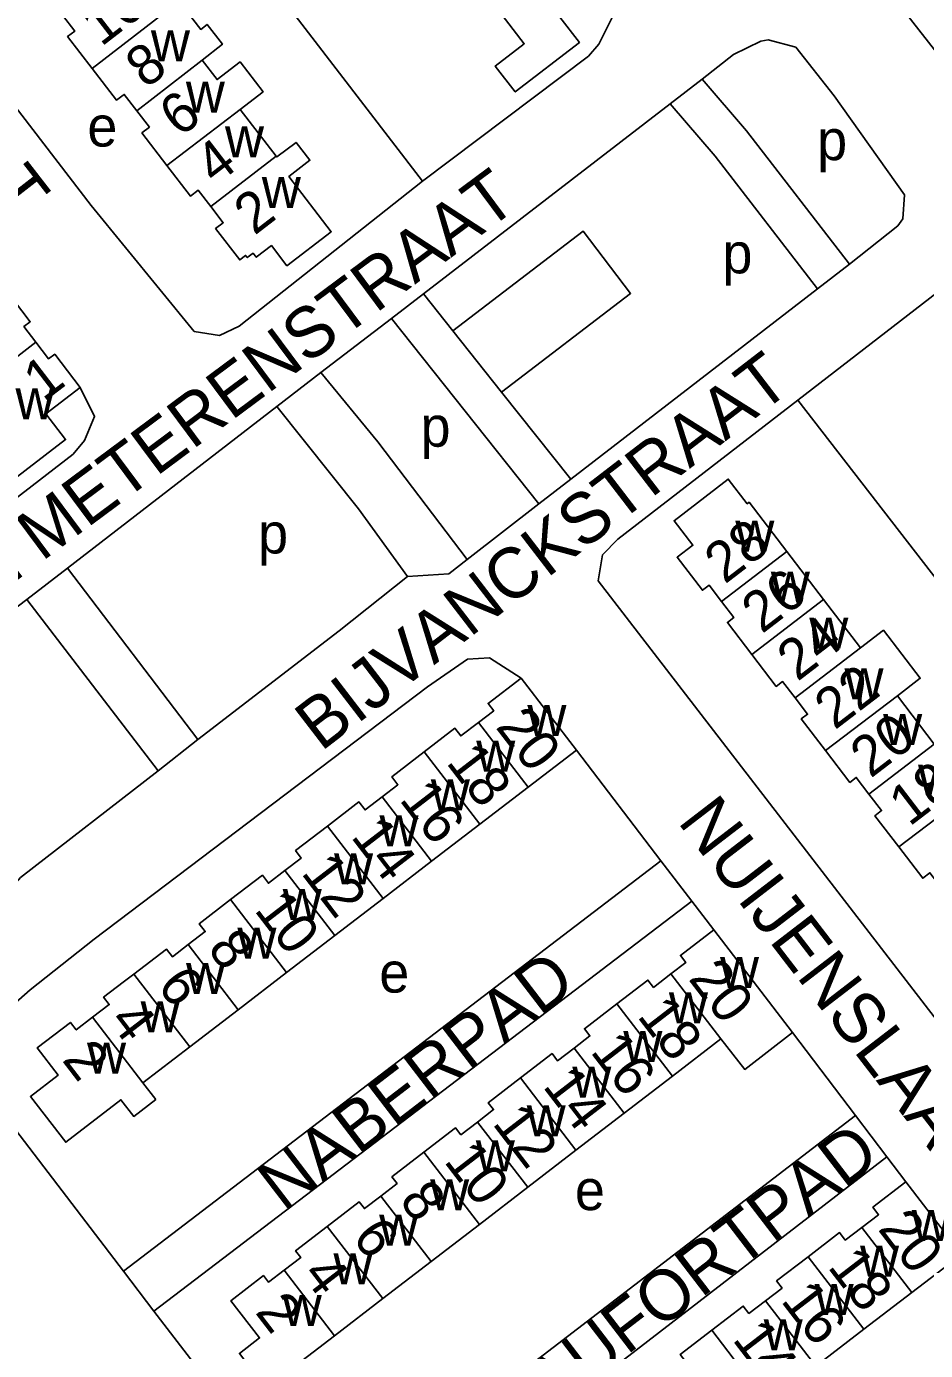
# Model space of a CAD drawing. Extents: x 158848 to 160613, y 385889 to 387762.
# Drawn here: x 159990.4 to 160079.5, y 386833.8 to 386965 of the extents above; entities that cross this region are included whole.
import ezdxf

# ---------------------------------------------------------------- set-up
doc = ezdxf.new("R2010")
doc.units = 0
for name, color, linetype in [('BLT_Basislijn', 7, 'Continuous'), ('BLT_Bebouwing', 7, 'Continuous'), ('BLT_Centroide', 7, 'Continuous'), ('BLT_Huisnummer', 7, 'Continuous'), ('BLT_Huisnummer_ tussenligend', 7, 'Continuous'), ('BLT_Onderverdeling_panden', 7, 'Continuous'), ('BLT_Straatnaam', 7, 'Continuous')]:
    doc.layers.add(name, color=color, linetype=linetype)

msp = doc.modelspace()

# ---------------------------------------------------------------- linework, layer by layer
at = {"layer": 'BLT_Basislijn'}
for p, q in [((160029.66, 386949.66), (160004.69, 386982.16)), ((160057.37, 386959.77), (160054.19, 386957.33)), ((160054.19, 386957.33), (160029.74, 386938.51)), ((160071.97, 386941.45), (160068.81, 386939.01)), ((160029.74, 386938.51), (160026.58, 386936.07)), ((160029.74, 386938.51), (160032.67, 386934.83)), ((160068.81, 386939.01), (160044.35, 386920.13)), ((160019.58, 386930.7), (160026.58, 386936.07)), ((160026.58, 386936.07), (160041.18, 386917.68)), ((160032.67, 386934.83), (160037.48, 386928.77)), ((160019.58, 386930.7), (160015.22, 386927.33)), ((160037.48, 386928.77), (160044.35, 386920.13)), ((160015.22, 386927.33), (159994.46, 386911.31)), ((160066.87, 386927.96), (160124.94, 386852.8)), ((160044.35, 386920.13), (160041.18, 386917.68)), ((160034.09, 386912.18), (160041.18, 386917.68)), ((159990.43, 386908.21), (159994.46, 386911.31)), ((159994.46, 386911.31), (160007.38, 386894.32)), ((160003.44, 386891.23), (159990.43, 386908.21)), ((160007.38, 386894.32), (160003.44, 386891.23)), ((160053.29, 386882.32), (160044.91, 386893.29)), ((160000.02, 386841.63), (160053.29, 386882.32)), ((160056.34, 386878.32), (160053.29, 386882.32)), ((160003.02, 386837.69), (160056.34, 386878.32)), ((160058.52, 386875.47), (160056.34, 386878.32)), ((160072.57, 386857.06), (160066.34, 386865.3)), ((160019.47, 386816.36), (160072.57, 386857.06)), ((160075.68, 386852.96), (160072.57, 386857.06)), ((160075.68, 386852.96), (160022.73, 386812.18)), ((160077.57, 386850.48), (160075.68, 386852.96)), ((160003.02, 386837.69), (160000.02, 386841.63)), ((160019.47, 386816.36), (160003.02, 386837.69))]:
    msp.add_line(p, q, dxfattribs=at)
for points in [[(160101.95, 386989.1), (160078.94, 386972.26), (160077.25, 386970.06), (160077.28, 386966.66), (160115.04, 386918.44), (160115.49, 386917.88)], [(160029.66, 386949.66), (160046.1, 386962.05), (160047.12, 386963.25), (160048.59, 386966.15), (160046.93, 386968.73)], [(159982.89, 386965.37), (159983.05, 386965.17), (159996.82, 386947.26), (160007.03, 386934.78), (160009.52, 386934.38), (160011.47, 386935.29), (160029.66, 386949.66)], [(160057.37, 386959.77), (160060.49, 386962.21), (160063.19, 386963.54), (160063.92, 386963.66), (160066.65, 386962.96), (160070.46, 386958.11), (160077.44, 386948.3), (160077.25, 386945.95), (160076.77, 386945.25), (160071.97, 386941.45)], [(160057.37, 386959.77), (160061.75, 386954.66), (160071.97, 386941.45)], [(160054.19, 386957.33), (160058.65, 386952.14), (160068.81, 386939.01)], [(160037.48, 386928.77), (160050.28, 386938.55), (160045.58, 386944.7), (160032.67, 386934.83)], [(160086.98, 386936.99), (160084.87, 386939.29), (160083.23, 386939.23), (160080.66, 386938.63), (160066.87, 386927.96)], [(160034.09, 386912.18), (160025.24, 386923.85), (160019.58, 386930.7)], [(159979.77, 386910.84), (159995.04, 386922.62), (159996.15, 386923.96), (159997.15, 386926.33), (159995.73, 386929.21)], [(160028.18, 386910.49), (160023.32, 386917.2), (160015.22, 386927.33)], [(160066.87, 386927.96), (160049.03, 386914.19), (160047.49, 386912.63), (160047.06, 386910.06), (160101.69, 386839.21)], [(160034.09, 386912.18), (160032.26, 386910.76), (160028.18, 386910.49)], [(160007.38, 386894.32), (160021.39, 386905.1), (160028.18, 386910.49)], [(159990.43, 386908.21), (159969.17, 386892.04), (159967.23, 386889.97), (159967.24, 386887.77), (159977.08, 386874.88), (159979.1, 386872.7), (159980.27, 386872.21), (159981.53, 386872.18), (159982.48, 386872.61), (159988.52, 386877.19), (159989.19, 386879.93), (159989.82, 386880.66), (160003.44, 386891.23)], [(160000.02, 386841.63), (159986.45, 386859.37), (159985.36, 386862.09), (159985.49, 386864.15), (159986.29, 386865.58), (159990.76, 386869.53), (159997.11, 386874.54), (160030.16, 386899.56), (160034.11, 386902.28), (160036.29, 386902.43), (160039.43, 386900.42)]]:
    msp.add_lwpolyline(points, dxfattribs=at)
at = {"layer": 'BLT_Bebouwing'}
for p, q in [((160015.15, 386952.15), (160011.58, 386956.78)), ((160069.41, 386908.2), (160065.75, 386912.98)), ((160073.07, 386903.42), (160069.41, 386908.2)), ((160044.91, 386893.29), (160039.43, 386900.42)), ((160080.38, 386893.88), (160076.72, 386898.66)), ((160040.12, 386889.61), (160044.91, 386893.29)), ((160035.34, 386885.94), (160040.12, 386889.61)), ((160030.55, 386882.26), (160035.34, 386885.94)), ((160025.76, 386878.58), (160030.55, 386882.26)), ((160020.97, 386874.91), (160025.76, 386878.58)), ((160066.34, 386865.3), (160058.52, 386875.47)), ((160016.18, 386871.23), (160020.97, 386874.91)), ((160001.06, 386871.09), (160000, 386870.28)), ((160011.39, 386867.55), (160016.18, 386871.23)), ((160006.6, 386863.88), (160011.39, 386867.55)), ((160001.95, 386860.31), (160006.6, 386863.88)), ((160054.43, 386860.98), (160059.22, 386864.66)), ((160003.21, 386858.65), (160001.95, 386860.31)), ((160049.65, 386857.31), (160054.43, 386860.98)), ((160044.86, 386853.63), (160049.65, 386857.31)), ((160040.08, 386849.95), (160044.86, 386853.63)), ((160035.29, 386846.27), (160040.08, 386849.95)), ((160083.07, 386843.3), (160077.57, 386850.48)), ((160030.51, 386842.59), (160035.29, 386846.27)), ((160078.15, 386839.53), (160083.07, 386843.3)), ((160025.72, 386838.92), (160030.51, 386842.59)), ((160020.94, 386835.24), (160025.72, 386838.92)), ((160073.39, 386835.88), (160078.15, 386839.53)), ((160068.63, 386832.22), (160073.39, 386835.88))]:
    msp.add_line(p, q, dxfattribs=at)
for points in [[(160046.93, 386968.73), (160043.28, 386965.92), (160045.21, 386963.42), (160038.84, 386958.52), (160036.87, 386961.08), (160039.74, 386963.28), (160036.02, 386968.12)], [(160007.83, 386961.65), (160009.83, 386963.23), (160008.31, 386965.2), (160007.68, 386964.71), (160005.53, 386967.49), (160004.15, 386966.42)], [(159993.98, 386966.13), (159995.2, 386964.55), (159994.48, 386963.99), (159996.91, 386960.84)], [(159996.91, 386960.84), (159999.34, 386957.69), (160000, 386958.2)], [(160011.58, 386956.78), (160013.86, 386958.53), (160011.58, 386961.48), (160009.3, 386959.73), (160007.83, 386961.65)], [(160000, 386958.2), (160000.09, 386958.26), (160001.33, 386956.64)], [(160001.33, 386956.64), (160002.58, 386955.03), (160001.84, 386954.45), (160004.33, 386951.21)], [(160008.66, 386947.16), (160009.9, 386945.54), (160009.15, 386944.97), (160011.54, 386941.87), (160012.12, 386942.31), (160012.29, 386942.09), (160012.87, 386942.53), (160013.18, 386942.13), (160014.68, 386943.28), (160016.22, 386941.28), (160020.61, 386944.66), (160016.41, 386950.13), (160018.49, 386951.74), (160017.12, 386953.51), (160015.21, 386952.07), (160015.15, 386952.15)], [(160004.33, 386951.21), (160006.67, 386948.18), (160007.42, 386948.77), (160008.66, 386947.16)], [(159988.39, 386938.86), (159990.78, 386935.74), (159990.15, 386935.25), (159991.33, 386933.71)], [(159991.33, 386933.71), (159992.6, 386932.05), (159993.2, 386932.51), (159995.73, 386929.21)], [(159995.73, 386929.21), (159992.32, 386926.61), (159994.28, 386924.05), (159988.24, 386919.42), (159982.49, 386926.9), (159984.79, 386928.67)], [(160065.75, 386912.98), (160062.02, 386917.84), (160061.84, 386917.7), (160059.95, 386920.15), (160054.59, 386916.02), (160056.46, 386913.59), (160054.89, 386912.39), (160057.39, 386909.12), (160058.05, 386909.63), (160059.28, 386908.02)], [(160059.28, 386908.02), (160060.5, 386906.42), (160059.87, 386905.93), (160062.29, 386902.76)], [(160076.72, 386898.66), (160078.98, 386900.4), (160075.33, 386905.16), (160073.07, 386903.42)], [(160062.29, 386902.76), (160064.72, 386899.6), (160065.34, 386900.07), (160066.58, 386898.46)], [(160039.43, 386900.42), (160036.16, 386897.91), (160036.71, 386897.19), (160035.2, 386896.03)], [(160066.58, 386898.46), (160067.82, 386896.84), (160067.2, 386896.37), (160069.61, 386893.23)], [(160035.2, 386896.03), (160033.45, 386894.69), (160032.87, 386895.44), (160029.83, 386893.1)], [(160029.83, 386893.1), (160026.61, 386890.63), (160027.21, 386889.85), (160025.65, 386888.64)], [(160069.61, 386893.23), (160072.01, 386890.08), (160072.65, 386890.57), (160073.9, 386888.93)], [(160025.65, 386888.64), (160023.96, 386887.35), (160023.35, 386888.15), (160020.25, 386885.76)], [(160073.9, 386888.93), (160075.15, 386887.29), (160074.49, 386886.78), (160076.86, 386883.68)], [(160020.25, 386885.76), (160017.07, 386883.32), (160017.63, 386882.58), (160016.02, 386881.35)], [(160076.86, 386883.68), (160079.23, 386880.58), (160079.94, 386881.12), (160081.26, 386879.4)], [(160016.02, 386881.35), (160014.39, 386880.09), (160013.78, 386880.88), (160010.63, 386878.46)], [(160010.63, 386878.46), (160007.52, 386876.07), (160008.12, 386875.3), (160006.44, 386874.01)], [(160058.52, 386875.47), (160055.22, 386872.94), (160055.76, 386872.24), (160054.27, 386871.1)], [(160006.44, 386874.01), (160004.87, 386872.8), (160004.28, 386873.57), (160001.06, 386871.09)], [(159996.96, 386866.8), (159998.6, 386868.06), (159998.04, 386868.78), (160000, 386870.28)], [(160054.27, 386871.1), (160052.55, 386869.77), (160051.99, 386870.49), (160048.93, 386868.14)], [(160048.93, 386868.14), (160045.7, 386865.66), (160046.25, 386864.95), (160044.69, 386863.75)], [(160003.21, 386858.65), (160001.04, 386856.98), (159999.77, 386858.63), (159994.3, 386854.42), (159990.8, 386858.95), (159993.54, 386861.06), (159991.46, 386863.76), (159994.76, 386866.29), (159995.33, 386865.55), (159996.96, 386866.8)], [(160059.22, 386864.66), (160061.59, 386861.64), (160066.34, 386865.3)], [(160044.69, 386863.75), (160043.04, 386862.48), (160042.49, 386863.2), (160039.36, 386860.79)], [(160039.36, 386860.79), (160036.17, 386858.34), (160036.7, 386857.65), (160035.1, 386856.42)], [(160035.1, 386856.42), (160033.46, 386855.16), (160032.94, 386855.84), (160029.8, 386853.42)], [(160029.8, 386853.42), (160026.63, 386850.99), (160027.14, 386850.33), (160025.52, 386849.08)], [(160077.57, 386850.48), (160074.3, 386847.97), (160074.85, 386847.24), (160073.21, 386845.98)], [(160025.52, 386849.08), (160023.9, 386847.84), (160023.39, 386848.51), (160020.22, 386846.07)], [(160020.22, 386846.07), (160017.08, 386843.66), (160017.59, 386842.99), (160015.95, 386841.73)], [(160073.21, 386845.98), (160071.56, 386844.72), (160070.99, 386845.46), (160067.87, 386843.06)], [(160067.87, 386843.06), (160064.75, 386840.67), (160065.29, 386839.96), (160063.65, 386838.7)], [(160015.95, 386841.73), (160014.4, 386840.54), (160013.89, 386841.2), (160010.66, 386838.71), (160013.5, 386835.02), (160011.51, 386833.49), (160014.4, 386829.72), (160016.39, 386831.25), (160016.15, 386831.56), (160020.94, 386835.24)], [(160063.65, 386838.7), (160062.01, 386837.45), (160061.45, 386838.18), (160058.32, 386835.79)], [(160058.32, 386835.79), (160055.2, 386833.39), (160055.76, 386832.66), (160054.15, 386831.42)]]:
    msp.add_lwpolyline(points, dxfattribs=at)
at = {"layer": 'BLT_Onderverdeling_panden'}
for p, q in [((159996.91, 386960.84), (160004.15, 386966.42)), ((160001.33, 386956.64), (160007.83, 386961.65)), ((160004.33, 386951.21), (160011.58, 386956.78)), ((160008.66, 386947.16), (160015.15, 386952.15)), ((159984.79, 386928.67), (159991.33, 386933.71)), ((160059.28, 386908.02), (160065.75, 386912.98)), ((160062.29, 386902.76), (160069.41, 386908.2)), ((160066.58, 386898.46), (160073.07, 386903.42)), ((160069.61, 386893.23), (160076.72, 386898.66)), ((160040.12, 386889.61), (160035.2, 386896.03)), ((160073.9, 386888.93), (160080.38, 386893.88)), ((160035.34, 386885.94), (160029.83, 386893.1)), ((160076.86, 386883.68), (160085.89, 386890.59)), ((160030.55, 386882.26), (160025.65, 386888.64)), ((160025.76, 386878.58), (160020.25, 386885.76)), ((160020.97, 386874.91), (160016.02, 386881.35)), ((160016.18, 386871.23), (160010.63, 386878.46)), ((160011.39, 386867.55), (160006.44, 386874.01)), ((160006.6, 386863.88), (160001.06, 386871.09)), ((160059.22, 386864.66), (160054.27, 386871.1)), ((160054.43, 386860.98), (160048.93, 386868.14)), ((160001.95, 386860.31), (159996.96, 386866.8)), ((160049.65, 386857.31), (160044.69, 386863.75)), ((160044.86, 386853.63), (160039.36, 386860.79)), ((160040.08, 386849.95), (160035.1, 386856.42)), ((160035.29, 386846.27), (160029.8, 386853.42)), ((160030.51, 386842.59), (160025.52, 386849.08)), ((160025.72, 386838.92), (160020.22, 386846.07)), ((160073.21, 386845.98), (160078.15, 386839.53)), ((160067.87, 386843.06), (160073.39, 386835.88)), ((160020.94, 386835.24), (160015.95, 386841.73)), ((160063.65, 386838.7), (160068.63, 386832.22)), ((160058.32, 386835.79), (160063.86, 386828.57))]:
    msp.add_line(p, q, dxfattribs=at)

# ---------------------------------------------------------------- texts
at = {"layer": 'BLT_Centroide'}
for s, p in [('w', (160002.74, 386961.53)), ('w', (160006.2, 386956.47)), ('e', (159996.44, 386953.1)), ('w', (160010.08, 386952.03)), ('p', (160068.77, 386951.75)), ('w', (160013.73, 386947)), ('p', (160059.38, 386940.53)), ('w', (159989.31, 386926.08)), ('p', (160029.46, 386923.35)), ('p', (160013.36, 386912.77)), ('w', (160060.66, 386912.94)), ('w', (160064.18, 386907.88)), ('w', (160067.99, 386903.34)), ('w', (160071.48, 386898.31)), ('w', (160040.05, 386894.67)), ('w', (160075.31, 386893.78)), ('w', (160034.98, 386891.14)), ('w', (160078.77, 386888.78)), ('w', (160030.48, 386887.3)), ('w', (160025.39, 386883.75)), ('w', (160020.89, 386879.97)), ('w', (160015.8, 386876.45)), ('w', (160011.31, 386872.61)), ('w', (160006.22, 386869.11)), ('e', (160025.37, 386869.25)), ('w', (160059.14, 386869.72)), ('w', (160054.08, 386866.19)), ('w', (160001.72, 386865.3)), ('w', (160049.56, 386862.36)), ('w', (159996.41, 386861.22)), ('w', (160044.5, 386858.84)), ('w', (160039.98, 386855.02)), ('w', (160034.94, 386851.52)), ('w', (160030.41, 386847.67)), ('e', (160044.76, 386847.69)), ('w', (160025.36, 386844.17)), ('w', (160078.14, 386844.64)), ('w', (160073.02, 386841.11)), ('w', (160020.83, 386840.33)), ('w', (160068.52, 386837.3)), ('w', (160015.8, 386836.2)), ('w', (160063.47, 386833.81))]:
    msp.add_text(s, height=4, dxfattribs=at).set_placement(p)
at = {"layer": 'BLT_Huisnummer'}
for s, rotation, p in [('6', 37.6197, (160005.6, 386953.95)), ('2', 37.6197, (160012.99, 386944.23)), ('1', 37.4279, (159992.1, 386927.73)), ('28', 37.414, (160059.61, 386909.67)), ('22', 37.414, (160070.51, 386895.22)), ('20', 307.5177, (160036.82, 386895.57)), ('18', 37.414, (160077.9, 386885.64)), ('14', 307.5177, (160022.48, 386884.7)), ('10', 307.5177, (160012.9, 386877.43)), ('6', 307.5177, (160003.27, 386869.89)), ('20', 307.5508, (160055.93, 386870.61)), ('2', 307.5177, (159993.85, 386862.57)), ('14', 307.5508, (160041.49, 386859.96)), ('10', 307.5508, (160031.7, 386852.53)), ('6', 307.5508, (160022.6, 386844.95)), ('20', 307.4974, (160074.71, 386845.81)), ('2', 307.5508, (160012.99, 386837.57)), ('14', 307.4974, (160060.29, 386834.87))]:
    msp.add_text(s, height=4, rotation=rotation, dxfattribs=at).set_placement(p)
at = {"layer": 'BLT_Huisnummer_ tussenligend'}
for s, rotation, p in [('10', 37.6197, (159997.8, 386962.93)), ('8', 37.6197, (160002.24, 386958.76)), ('4', 37.6197, (160009.13, 386949.19)), ('26', 37.414, (160063.29, 386904.75)), ('24', 37.414, (160066.81, 386900.02)), ('20', 37.414, (160074.06, 386890.43)), ('18', 307.5177, (160031.92, 386892.05)), ('16', 307.5177, (160027.28, 386888.37)), ('12', 307.5177, (160017.55, 386881.1)), ('8', 307.5177, (160008.24, 386873.57)), ('18', 307.5508, (160050.85, 386866.91)), ('4', 307.5177, (159998.48, 386866.42)), ('16', 307.5508, (160046.21, 386863.4)), ('12', 307.5508, (160036.5, 386856.28)), ('8', 307.5508, (160027.25, 386848.62)), ('18', 307.4974, (160069.73, 386842.06)), ('4', 307.5508, (160017.62, 386841.27)), ('16', 307.4974, (160065.09, 386838.71))]:
    msp.add_text(s, height=4, rotation=rotation, dxfattribs=at).set_placement(p)
at = {"layer": 'BLT_Straatnaam'}
for s, rotation, p in [('VAN AITZEMASTRAAT', 307.8301, (159945.46, 387001.57)), ('VAN METERENSTRAAT', 36.625, (159979.4, 386902.61)), ('BIJVANCKSTRAAT', 37.5411, (160019.59, 386893.07)), ('NUIJENSLAAN', 307.5472, (160054.86, 386886.18)), ('NABERPAD', 37.5, (160015.93, 386847.4)), ('DE BEAUFORTPAD', 37.5, (160026.61, 386815.39))]:
    msp.add_text(s, height=5, rotation=rotation, dxfattribs=at).set_placement(p)

doc.saveas('drawing.dxf')
